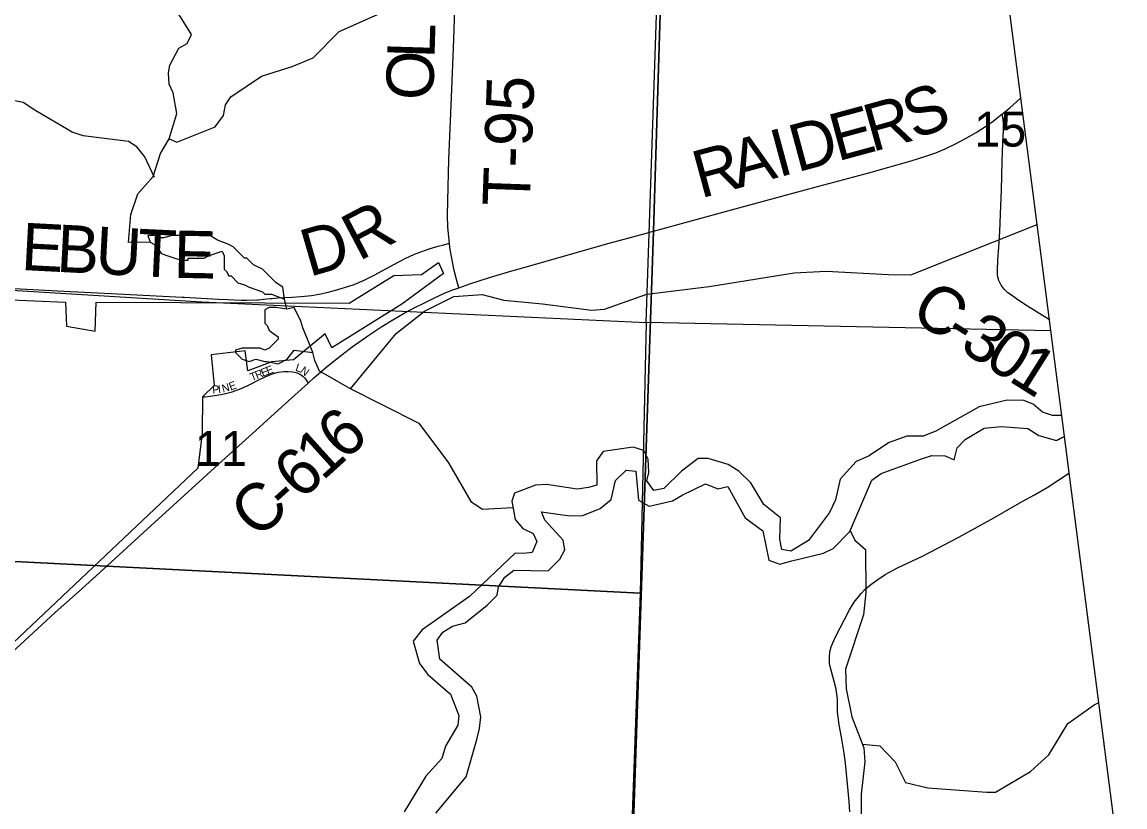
# Model space of a CAD drawing. Extents: x 0 to 34, y 0 to 22.
# Drawn here: x 25.417 to 26.74, y 14.847 to 15.788 of the extents above; entities that cross this region are included whole.
import ezdxf

# ---------------------------------------------------------------- set-up
doc = ezdxf.new("R2010")
doc.units = 0
for name, color, linetype in [('GM_X_Corporation', 7, 'Continuous'), ('GM_X_County_Road', 7, 'Continuous'), ('GM_X_County_Road_Text', 7, 'Continuous'), ('GM_X_Minor_Lake', 7, 'Continuous'), ('GM_X_Minor_River', 7, 'Continuous'), ('GM_X_Section', 7, 'Continuous'), ('GM_X_Section_Text', 7, 'Continuous'), ('GM_X_Township', 7, 'Continuous'), ('GM_X_Township_Road', 7, 'Continuous'), ('GM_X_Township_Road_Text', 7, 'Continuous'), ('GM_X_Township_Subdivision', 7, 'Continuous'), ('GM_X_Township_Subdivision_Text', 7, 'Continuous'), ('SH_Text', 7, 'Continuous')]:
    doc.layers.add(name, color=color, linetype=linetype)

msp = doc.modelspace()

# ---------------------------------------------------------------- linework, layer by layer
at = {"layer": 'GM_X_Corporation'}
msp.add_lwpolyline([(25.3574, 15.4568), (25.4692, 15.452), (25.4704, 15.4235), (25.5049, 15.4175), (25.5061, 15.452), (25.8095, 15.4509), (25.8309, 15.4639), (25.863, 15.4842), (25.8964, 15.4854), (25.9166, 15.4996), (25.9225, 15.4866), (25.8726, 15.4497), (25.7889, 15.3973), (25.7809, 15.414), (25.7429, 15.383), (25.7167, 15.3807), (25.6881, 15.3699), (25.6846, 15.3937), (25.6441, 15.389), (25.6477, 15.3521), (25.6335, 15.3384), (25.6334, 15.295), (25.6279, 15.253), (25.399, 15.0362)], dxfattribs=at)
at = {"layer": 'GM_X_County_Road'}
for points in [[(26.5928, 15.6778), (26.5936, 15.6784), (26.6018, 15.6851), (26.6105, 15.6927), (26.6151, 15.6971)], [(26.1741, 15.5372), (26.1747, 15.5373), (26.268, 15.5627), (26.3607, 15.588), (26.4326, 15.6074), (26.4835, 15.6217), (26.5013, 15.6272), (26.513, 15.6314), (26.5245, 15.6361), (26.5358, 15.6414), (26.5496, 15.6487), (26.5617, 15.6556), (26.5727, 15.6627), (26.5818, 15.669), (26.5928, 15.6778)], [(26.6495, 15.431), (26.6201, 15.4493), (26.6098, 15.456), (26.6038, 15.4604), (26.5997, 15.4634), (26.5952, 15.4677), (26.5915, 15.4726), (26.5889, 15.4782), (26.5873, 15.4842), (26.587, 15.4904), (26.5875, 15.5027), (26.5888, 15.5182), (26.5899, 15.5368), (26.5913, 15.5678), (26.5921, 15.5865), (26.5929, 15.621), (26.5936, 15.6431), (26.5943, 15.6585), (26.5944, 15.6623), (26.5943, 15.6665), (26.594, 15.671), (26.5928, 15.6778)], [(26.0106, 15.4914), (26.1212, 15.523), (26.1661, 15.535), (26.1741, 15.5372)], [(25.7413, 15.4583), (25.752, 15.459), (25.7644, 15.4602), (25.7737, 15.4616), (25.7829, 15.4635), (25.7919, 15.4659), (25.8038, 15.4696), (25.8157, 15.4734), (25.8274, 15.4786), (25.8394, 15.4845), (25.863, 15.4973), (25.8767, 15.5044), (25.888, 15.5096), (25.8966, 15.513), (25.9054, 15.5161), (25.9164, 15.5192), (25.9231, 15.521), (25.9297, 15.5228)], [(25.9411, 15.4694), (25.9544, 15.4741), (25.978, 15.4818), (26.0048, 15.4898), (26.0106, 15.4914)], [(25.352, 15.4711), (25.3554, 15.471), (25.3729, 15.47), (25.4079, 15.4683), (25.4671, 15.4653), (25.5079, 15.4633), (25.6093, 15.4583), (25.6116, 15.4582), (25.6527, 15.4557), (25.6644, 15.4552), (25.6713, 15.4548), (25.68, 15.4547), (25.6869, 15.4545), (25.6993, 15.4549), (25.7007, 15.455), (25.7066, 15.4556), (25.7146, 15.4565), (25.7166, 15.4566), (25.7239, 15.4573), (25.7409, 15.4583), (25.7413, 15.4583)], [(25.8891, 15.446), (25.8973, 15.4503), (25.9112, 15.4571), (25.9253, 15.4635), (25.934, 15.4669), (25.9411, 15.4694)], [(25.7605, 15.3551), (25.7673, 15.3613), (25.7837, 15.3755), (25.8006, 15.3891), (25.813, 15.3984), (25.8332, 15.4127), (25.8488, 15.423), (25.8619, 15.4311), (25.8754, 15.4388), (25.8891, 15.446)], [(25.398, 15.026), (25.4045, 15.0316), (25.4569, 15.0799), (25.4848, 15.1046), (25.5192, 15.136), (25.5673, 15.1799), (25.6568, 15.2615), (25.6937, 15.2947), (25.7329, 15.33), (25.7605, 15.3551)], [(26.4102, 14.8408), (26.4093, 14.8532), (26.4074, 14.8744), (26.4048, 14.8991), (26.4034, 14.9114), (26.4001, 14.9306), (26.3972, 14.945), (26.3959, 14.9542), (26.3953, 14.9604), (26.3952, 14.9665), (26.3951, 14.9758), (26.3945, 14.9819), (26.3935, 14.988), (26.3913, 14.997), (26.3879, 15.009), (26.3866, 15.0151), (26.3858, 15.0188), (26.3855, 15.0233), (26.3857, 15.0276), (26.386, 15.0316), (26.3866, 15.0344), (26.3877, 15.0387), (26.3898, 15.0434), (26.3933, 15.0516), (26.4035, 15.0715), (26.4098, 15.0833), (26.4153, 15.0925), (26.4235, 15.1026), (26.4282, 15.1074), (26.4351, 15.1134), (26.4436, 15.1196), (26.4525, 15.1256), (26.4673, 15.1333), (26.4973, 15.1476), (26.5409, 15.1704), (26.5605, 15.1811), (26.5829, 15.1936), (26.6167, 15.2131), (26.6313, 15.2212), (26.6465, 15.23), (26.6607, 15.2392), (26.6699, 15.2452), (26.6732, 15.2473)]]:
    msp.add_lwpolyline(points, dxfattribs=at)
at = {"layer": 'GM_X_Minor_Lake'}
for points in [[(25.7318, 15.4558), (25.7299, 15.47), (25.7218, 15.4754), (25.7137, 15.4835), (25.7056, 15.4916), (25.6948, 15.497), (25.6867, 15.505), (25.684, 15.505), (25.6732, 15.5158), (25.6705, 15.5185), (25.6651, 15.5212), (25.6516, 15.5266), (25.6381, 15.5347), (25.6327, 15.5347), (25.6246, 15.532), (25.6111, 15.532), (25.5976, 15.532), (25.5868, 15.5293), (25.5814, 15.5293), (25.5761, 15.532), (25.568, 15.532), (25.5707, 15.5239)], [(25.5707, 15.5239), (25.5761, 15.5212), (25.5788, 15.5186), (25.5842, 15.5104), (25.5922, 15.5078), (25.6003, 15.505), (25.6084, 15.5024), (25.6165, 15.5024), (25.6165, 15.505), (25.6192, 15.505), (25.6273, 15.505), (25.6354, 15.505), (25.6408, 15.5078), (25.6489, 15.5104), (25.657, 15.5131), (25.6597, 15.5078), (25.6597, 15.505), (25.6597, 15.5024), (25.6597, 15.497), (25.6597, 15.4916), (25.6624, 15.4889), (25.6651, 15.4835), (25.6678, 15.4835), (25.6759, 15.4754), (25.684, 15.4727), (25.6894, 15.47), (25.7056, 15.4646), (25.7083, 15.4619), (25.711, 15.4619), (25.7164, 15.4619), (25.7318, 15.4558)], [(25.7348, 15.4437), (25.7218, 15.4457), (25.7191, 15.4457), (25.7137, 15.4457), (25.7083, 15.443), (25.7083, 15.4295), (25.7083, 15.4268), (25.711, 15.4241), (25.7137, 15.4187), (25.7164, 15.416), (25.7245, 15.4106), (25.7245, 15.4079), (25.7137, 15.3971), (25.7083, 15.3944), (25.7029, 15.3971), (25.6813, 15.3971), (25.6732, 15.3944), (25.6732, 15.3917), (25.6813, 15.3836), (25.6894, 15.3809), (25.6975, 15.3836), (25.7083, 15.3809), (25.711, 15.3809), (25.7245, 15.3782), (25.7353, 15.3836), (25.7434, 15.3944), (25.7661, 15.3918)], [(25.7661, 15.3918), (25.7595, 15.4079), (25.7541, 15.4214), (25.7515, 15.4295), (25.7434, 15.4457), (25.7348, 15.4437)]]:
    msp.add_lwpolyline(points, dxfattribs=at)
at = {"layer": 'GM_X_Minor_River'}
for points in [[(25.5744, 15.6029), (25.5834, 15.6306), (25.5935, 15.6481), (25.6028, 15.6785), (25.5986, 15.7031), (25.5936, 15.7137), (25.5928, 15.727), (25.5946, 15.7365), (25.6051, 15.7566), (25.6153, 15.7623), (25.6206, 15.773), (25.5993, 15.8071), (25.6043, 15.8571), (25.6005, 15.8678), (25.5861, 15.8817), (25.5735, 15.8889), (25.5518, 15.9215), (25.5468, 15.9381), (25.5471, 15.9533), (25.5444, 15.9647), (25.5087, 16.012), (25.5056, 16.0279), (25.4907, 16.04), (25.487, 16.0339)], [(25.5935, 15.6481), (25.603, 15.6439), (25.6487, 15.6623), (25.6589, 15.676), (25.6611, 15.6889), (25.6675, 15.6984), (25.7045, 15.7232), (25.7411, 15.7347), (25.7665, 15.745), (25.7977, 15.7766), (25.8824, 15.8148), (25.9274, 15.8268), (25.9542, 15.8382), (25.9829, 15.8634), (26.0286, 15.8836), (26.0512, 15.9065), (26.053, 15.9304), (26.0666, 15.9414), (26.0908, 15.9506)], [(25.5761, 15.6015), (25.5645, 15.6263), (25.5549, 15.6385), (25.5447, 15.6449), (25.4905, 15.6515), (25.4773, 15.656), (25.4336, 15.6817), (25.4184, 15.6915), (25.3942, 15.6963), (25.354, 15.7163), (25.2896, 15.7146), (25.2359, 15.706), (25.1806, 15.7119), (25.1494, 15.7384), (25.101, 15.734), (25.0912, 15.7351), (25.0813, 15.7416), (25.0514, 15.7456), (25.0408, 15.7471), (24.9975, 15.7674), (24.9714, 15.773), (24.919, 15.7937), (24.9079, 15.8229)], [(25.5707, 15.5239), (25.5448, 15.5235), (25.5477, 15.5572), (25.5559, 15.5819), (25.5744, 15.6029)], [(25.8113, 15.3483), (25.8657, 15.4147), (25.8997, 15.4414), (25.9349, 15.459), (25.969, 15.4614), (25.9952, 15.4547), (26.0414, 15.4503), (26.1002, 15.4426), (26.1158, 15.4438), (26.1665, 15.4619), (26.2411, 15.4709), (26.3434, 15.4873), (26.3816, 15.4893), (26.4563, 15.4851), (26.4832, 15.4849), (26.6347, 15.5451)], [(25.7348, 15.4437), (25.7318, 15.4558)], [(25.8075, 15.3502), (25.7867, 15.3623), (25.7738, 15.3694), (25.7684, 15.382), (25.7661, 15.3918)], [(25.8075, 15.3502), (25.8931, 15.307), (25.9286, 15.2594), (25.9553, 15.2132), (25.9694, 15.2038), (26.006, 15.2058)], [(26.5988, 15.3347), (26.5651, 15.3266), (26.5133, 15.2972), (26.4981, 15.2914), (26.4784, 15.2914), (26.4572, 15.2837), (26.4323, 15.2673), (26.4176, 15.2611), (26.3983, 15.2398)], [(26.6643, 15.3161), (26.6531, 15.316), (26.6409, 15.3201), (26.6299, 15.3296), (26.6189, 15.3341), (26.5988, 15.3347)], [(26.326, 15.1378), (26.3404, 15.1417), (26.3786, 15.1509), (26.39, 15.1567), (26.41, 15.1769), (26.4362, 15.2388), (26.4476, 15.2465), (26.496, 15.2641), (26.5085, 15.2683), (26.5244, 15.2677), (26.535, 15.2631), (26.5388, 15.2776), (26.5482, 15.2875), (26.5713, 15.3009), (26.5917, 15.3028), (26.6236, 15.3007), (26.6365, 15.292), (26.6577, 15.2861)], [(26.6577, 15.2861), (26.6675, 15.2909)], [(26.6675, 15.2909), (26.6577, 15.2861)], [(26.3983, 15.2398), (26.3927, 15.2151), (26.3856, 15.1999), (26.3604, 15.1664), (26.3392, 15.1534), (26.3286, 15.1553), (26.3259, 15.1678), (26.3269, 15.1936), (26.3067, 15.2094), (26.2911, 15.2355), (26.277, 15.2495), (26.2641, 15.2574), (26.2401, 15.2645), (26.228, 15.2645), (26.208, 15.2496), (26.1869, 15.2286), (26.1748, 15.2263), (26.1664, 15.238), (26.169, 15.2479), (26.1681, 15.2638), (26.1628, 15.2741), (26.1503, 15.2782), (26.1143, 15.2731), (26.106, 15.2617), (26.1065, 15.2328), (26.0967, 15.2298), (26.083, 15.2278), (26.0462, 15.2333), (26.033, 15.2325), (26.008, 15.2229), (26.0046, 15.2134), (26.0085, 15.1914), (26.0177, 15.1805), (26.0302, 15.1748), (26.0344, 15.165), (26.0292, 15.1517), (26.0189, 15.1505), (26.0087, 15.1509), (25.954, 15.099), (25.8969, 15.0593), (25.8864, 15.0456), (25.8937, 15.0187), (25.904, 15.0055), (25.931, 14.9821), (25.941, 14.9563), (25.9399, 14.9446), (25.9249, 14.9198), (25.9208, 14.905), (25.9015, 14.8837), (25.8756, 14.8407)], [(25.9135, 14.8394), (25.9497, 14.8828), (25.9627, 14.9276), (25.9657, 14.9409), (25.9675, 14.9549), (25.9625, 14.9796), (25.9568, 14.9902), (25.9183, 15.0241), (25.9152, 15.0469), (25.922, 15.0564), (25.9333, 15.0636), (25.9488, 15.0675), (25.9749, 15.0889), (25.9869, 15.1007), (25.9888, 15.1105), (25.9963, 15.1223), (26.0069, 15.1307), (26.0482, 15.1298), (26.0622, 15.1439), (26.0682, 15.1549), (26.0662, 15.1667), (26.0441, 15.1905), (26.0403, 15.2007), (26.0627, 15.1974), (26.0744, 15.1959), (26.0896, 15.1963), (26.1104, 15.2048), (26.1236, 15.2155), (26.1288, 15.2382), (26.1417, 15.2508), (26.1534, 15.2494), (26.1566, 15.2145), (26.1692, 15.2073), (26.1975, 15.2139), (26.2089, 15.2208), (26.2369, 15.2342), (26.2517, 15.2282), (26.2638, 15.2309), (26.2844, 15.1934), (26.3057, 15.1779), (26.3127, 15.1427), (26.326, 15.1378)], [(26.4105, 15.1781), (26.4161, 15.1666), (26.429, 15.1553), (26.4293, 15.1041), (26.4264, 15.0772), (26.4047, 15.0118), (26.4055, 14.9883), (26.4125, 14.9549), (26.4267, 14.9178), (26.4279, 14.9008), (26.4236, 14.862), (26.4242, 14.796)], [(26.4251, 14.9219), (26.446, 14.9202), (26.4643, 14.9009), (26.4769, 14.8759), (26.5035, 14.8696), (26.5744, 14.8646), (26.5846, 14.8646), (26.6266, 14.8891), (26.6485, 14.9093), (26.6714, 14.9466), (26.7032, 14.9691), (26.7087, 14.972)]]:
    msp.add_lwpolyline(points, dxfattribs=at)
at = {"layer": 'GM_X_Section'}
msp.add_lwpolyline([(26.6512, 15.4179), (26.1658, 15.4276), (26.1831, 15.9395), (26.1833, 15.9453), (26.585, 15.9305)], dxfattribs=at)
for points in [[(25.6327, 15.4525), (26.1658, 15.4276), (26.1585, 15.1031), (25.1469, 15.1542), (25.1568, 15.4818)], [(25.1469, 15.1542), (26.1585, 15.1031), (26.1524, 14.9369), (26.1341, 14.4312), (26.1236, 14.1064), (25.1079, 14.1514)]]:
    msp.add_lwpolyline(points, close=True, dxfattribs=at)
at = {"layer": 'GM_X_Township'}
for points in [[(26.2189, 16.9294), (26.2007, 16.3781), (26.2005, 16.374), (26.2005, 16.3538), (26.1991, 16.332), (26.1747, 15.5373), (26.1374, 14.4382), (26.1244, 14.1)], [(26.1244, 14.1), (26.1374, 14.4382), (26.1747, 15.5373), (26.1991, 16.332), (26.2005, 16.3538), (26.2005, 16.374), (26.2007, 16.3781), (26.2189, 16.9294)]]:
    msp.add_lwpolyline(points, dxfattribs=at)
at = {"layer": 'GM_X_Township_Road'}
for points in [[(25.9322, 15.6978), (25.9346, 15.7567), (25.9366, 15.814), (25.9371, 15.8278)], [(25.9297, 15.5228), (25.9289, 15.5301), (25.9279, 15.5425), (25.9275, 15.5558), (25.9279, 15.5735), (25.9292, 15.6231), (25.931, 15.6695), (25.9322, 15.6978)], [(25.9411, 15.4694), (25.938, 15.481), (25.9356, 15.4901), (25.9329, 15.5023), (25.9303, 15.5177), (25.9297, 15.5228)]]:
    msp.add_lwpolyline(points, dxfattribs=at)
at = {"layer": 'GM_X_Township_Subdivision'}
msp.add_lwpolyline([(25.6334, 15.3384), (25.6368, 15.3387), (25.6429, 15.3395), (25.6558, 15.3415), (25.6613, 15.3427), (25.6692, 15.3447), (25.6766, 15.3472), (25.6819, 15.3494), (25.6896, 15.3531), (25.7029, 15.3596), (25.7125, 15.3641), (25.7176, 15.366), (25.7243, 15.368), (25.731, 15.3688), (25.7363, 15.3688), (25.7418, 15.3684), (25.7457, 15.3678), (25.7498, 15.3662), (25.7522, 15.3647), (25.754, 15.3633), (25.7558, 15.3615), (25.7573, 15.3596), (25.7583, 15.3582), (25.7605, 15.3551)], dxfattribs=at)
at = {"layer": 'SH_Text'}
msp.add_lwpolyline([(26.5011, 16.5809), (27.1585, 14.8261), (26.7275, 14.8261)], close=True, dxfattribs=at)

# ---------------------------------------------------------------- texts
at = {"layer": 'GM_X_County_Road_Text'}
for s, rotation, p in [('S', 21.3099, (26.4874, 15.6465)), ('R', 15.5998, (26.4366, 15.632)), ('E', 15.1275, (26.3951, 15.6208)), ('D', 15.1251, (26.3468, 15.6077)), ('A', 15.1251, (26.276, 15.5886)), ('I', 15.123, (26.3243, 15.6016)), ('R', 15.123, (26.231, 15.5764)), ('R', 27.7097, (25.8211, 15.5007)), ('E', 357.0078, (25.4153, 15.4908)), ('B', 357.0068, (25.4577, 15.4886)), ('D', 16.2331, (25.7617, 15.4822)), ('U', 357.0079, (25.5043, 15.4862)), ('T', 357.2391, (25.5545, 15.4835)), ('E', 358.7716, (25.5986, 15.4814)), ('C', 326.3797, (26.4805, 15.4345)), ('3', 327.7858, (26.5399, 15.3957)), ('-', 327.7729, (26.5203, 15.4081)), ('0', 327.7925, (26.5693, 15.3772)), ('1', 327.7945, (26.5987, 15.3587)), ('6', 42.2798, (25.8036, 15.2605)), ('1', 42.1123, (25.7775, 15.2369)), ('6', 42.0678, (25.7515, 15.2134)), ('C', 42.0484, (25.6995, 15.1665)), ('-', 42.0496, (25.7342, 15.1978))]:
    msp.add_text(s, height=0.0568, rotation=rotation, dxfattribs=at).set_placement(p)
at = {"layer": 'GM_X_Section_Text'}
for s, p in [('15', (26.5593, 15.6387)), ('11', (25.6246, 15.2557))]:
    msp.add_text(s, height=0.04186, rotation=0, dxfattribs=at).set_placement(p)
at = {"layer": 'GM_X_Township_Road_Text'}
for s, height, rotation, p in [('L', 0.0568, 88.2255, (25.9118, 15.7438)), ('O', 0.0568, 88.2329, (25.9102, 15.6938)), ('T-95', 0.05682, 87.9678, (26.0261, 15.5665))]:
    msp.add_text(s, height=height, rotation=rotation, dxfattribs=at).set_placement(p)
at = {"layer": 'GM_X_Township_Subdivision_Text'}
for s, rotation, p in [('R', 21.5444, (25.6989, 15.3597)), ('E', 21.5376, (25.7059, 15.3625)), ('E', 21.5475, (25.7121, 15.3649)), ('L', 341.8588, (25.7443, 15.37)), ('N', 323.0645, (25.7499, 15.3683)), ('T', 21.5376, (25.6927, 15.3573)), ('P', 4.9248, (25.6458, 15.3424)), ('I', 5.8514, (25.6526, 15.343)), ('N', 14.0722, (25.6581, 15.3437)), ('E', 20.1836, (25.6673, 15.346))]:
    msp.add_text(s, height=0.00947, rotation=rotation, dxfattribs=at).set_placement(p)

doc.saveas('drawing.dxf')
